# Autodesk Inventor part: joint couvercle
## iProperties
Created: 2001-11
Part Number: joint couvercle
Material: Par défaut
Document SubType Name: Modélisation
Designer: User
Control State: 0
Master: False
Checked Out: False
Shininess: 20.0
Length Units: 11269
Angle Units: 11279
Time Units: 11290
Mass Units: 11283
Length Display Precision: 3
Angle Display Precision: 2
Density: 0.0
Volumn: 0.0
Area: 0.0
PropertySet Name: Model Information
Author: User
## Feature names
1. Extrusion1
2. Extrusion2
3. Symétrie1 [Mirror]
